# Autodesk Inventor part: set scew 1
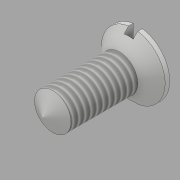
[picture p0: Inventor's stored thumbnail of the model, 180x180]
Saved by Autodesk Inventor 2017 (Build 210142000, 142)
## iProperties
Created: 2016-06
Part Number: set scew 1
Material: Generic
Document SubType Name: Modeling
Designer: CADCIM
Density: 1 g/cm^3
Appearance: Default
Author: CADCIM
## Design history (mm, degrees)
sketch "Sketch1"
  geometry: C1 r 3 at (0, 0); 1 further point
  constraints: 1 centre point, 1 coincident
  dimensions: "d0" = 6 diameter of C1
extrude "Extrusion1" new body sketch "Sketch1" distance "d1" = 14; taper "d2" = 0 deg
sketch "Sketch2"
  geometry: L1 (14, -3)-(14, 3) reference; L2 (14, 0)-(14, -3); L3 (14, -3)-(17, -6); L4 (17, -6)-(17, 0); L5 (17, 0)-(14, 0); 1 further point
  constraints: 8 end point, 2 vertical, 1 midpoint, 1 perpendicular
  dimensions: "d4" = 3 distance of L2.start L2.end; "d5" = 6 distance of L4.end L3.end; "d6" = 3 distance from line of L1.start L4
revolve "Revolution1" sketch "Sketch2" stored, may be unused: angle "d7" = 90 deg
sketch "Sketch3"
  geometry: C1 r 5.25 at (0, 0); 1 further point
  constraints: 1 centre point, 1 coincident
  dimensions: "d8" = 10.5 diameter of C1
extrude "Extrusion2" sketch "Sketch3" distance "d9" = 14; taper "d10" = 0 deg
sketch "Sketch4"
  geometry: L1 (-0.75, 8.347)-(0.75, 8.347); L2 (0.75, 8.347)-(0.75, -8.125); L3 (0.75, -8.125)-(-0.75, -8.125); L4 (-0.75, -8.125)-(-0.75, 8.347); L5 (0, 0)-(0, 6.165)
  constraints: 10 end point, 3 parallel, 1 horizontal, 1 perpendicular, 1 other
  dimensions: "d11" = 1.5 distance of L1.start L1.end
extrude "Extrusion3" cut sketch "Sketch4" distance "d12" = 1.5; taper "d13" = 0 deg
sketch "Sketch5"
  geometry: L1 (3, 0)-(3, 3); L2 (3, 3)-(3, -3) reference; L3 (3, 3)-(1.268, 0); L4 (1.268, 0)-(3, 0); 1 further point
  constraints: 6 end point, 1 midpoint, 1 perpendicular, 1 vertical
  dimensions: "d16" = 3 distance of L1.start L1.end; "d17" = 60 deg angle of L4 L3
revolve "Revolution2" sketch "Sketch5" stored, may be unused: angle "d18" = 90 deg
thread "Thread2" dims "d19" = 10, "d20" = 0
body "Solid1"
